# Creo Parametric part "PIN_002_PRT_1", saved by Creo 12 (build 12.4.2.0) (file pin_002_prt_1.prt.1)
Units: Custom; MM, KILOGRAM, SECS

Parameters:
  PTC_WM_ITERATION = "0"
  PTC_WM_VERSION = "-.0"
  PTC_WM_LIFECYCLE_STATE = "In Work"
  PTC_WM_LIFECYCLE = "MO_CADDocument"
  PTC_WM_CREATED_BY = "Maximilian Roepper (Z0017RMS: MO)"
  PTC_WM_CREATED_ON = "18-Sep-26 11:36:42 AM"
  PTC_WM_MODIFIED_BY = "Maximilian Roepper (Z0017RMS: MO)"
  PTC_WM_MODIFIED_ON = "18-Sep-26 11:36:46 AM"
  PDMLINKNUMBER = "PDM000071455231"
  PTC_WM_NAME = "pin_002_prt_1.prt"
  PTC_WM_NUMBER = "PDM000071455231"

Other parameters: WEIGHT, WEIGHT_FACTOR, WEIGHT_ADD, _MASS_TEMP, _DIFF_TEMP, MC_ERRORS, SUPPLIER

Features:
  1. coordinate system
  2. datum plane "PRT_YZ"
  3. datum plane "PRT_XY"
  4. datum plane "PRT_XZ"
  5. coordinate system
  6. datum axis
  7. datum axis
  8. datum axis
  9. coordinate system
  10. imported feature
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
Other named items: PRT, SIEMENS_MO, DRW_VIEW_ORG, PRT_X, PRT_Y, PRT_Z, CS0, ROUGH_GROB

Layers: 00_STD_CSYS-KSYS, 01_STD_PLANES-EBENEN, 02_STD_AXES-ACHSEN, 03_STD_CSYS-KSYS, 24_IMPORT_FEAT-IMPORT_KE

Surfaces: 9 plane, 1 cylinder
